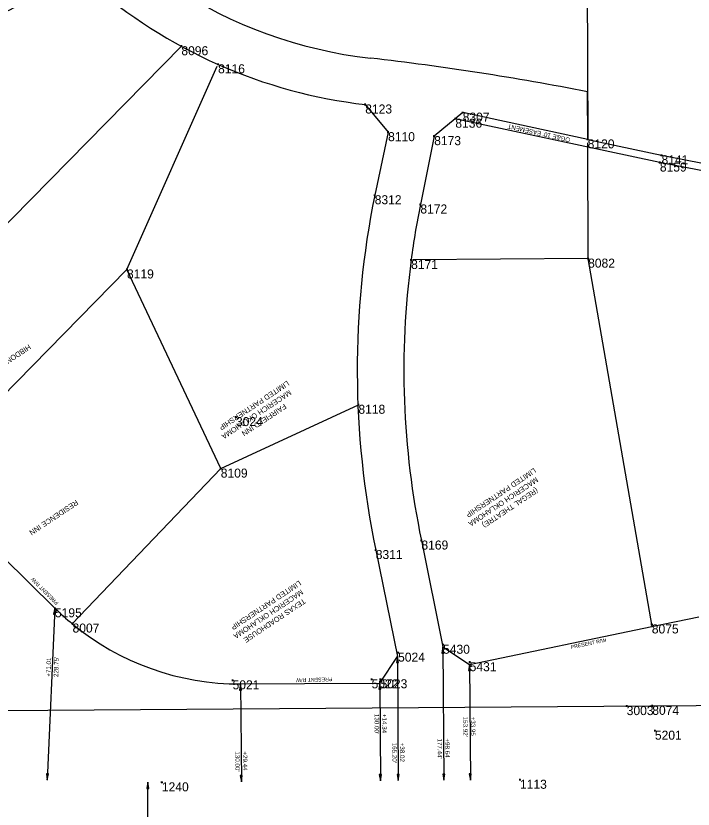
# Model space of a CAD drawing. Extents: x 2145146 to 2158053, y 137507 to 150829.
# Drawn here: x 2151434 to 2152334, y 142870 to 143925 of the extents above; entities that cross this region are included whole.
import ezdxf

# ---------------------------------------------------------------- set-up
doc = ezdxf.new("R2010")
doc.units = 0
for name, color, linetype in [('ALIGN_Cogo Points', 7, 'Continuous'), ('ALIGN_ROW Dimension', 7, 'Continuous'), ('ALIGN_ROW Line', 7, 'Continuous'), ('ALIGN_ROW Text', 7, 'Continuous'), ('PLSS_Easement', 7, 'Continuous'), ('PLSS_Property Line', 7, 'Continuous'), ('PLSS_Section Line', 7, 'Continuous'), ('PLSS_Text', 7, 'Continuous'), ('PLSS_Text_TURNED OFF', 7, 'Continuous')]:
    doc.layers.add(name, color=color, linetype=linetype)

# ---------------------------------------------------------------- blocks, each defined once
blk = doc.blocks.new('Arrowhd')
at = {"layer": 'PLSS_Property Line'}
blk.add_lwpolyline([(0.125, -0.021), (0.125, 0.021), (0, 0)], close=True, dxfattribs=at)

msp = doc.modelspace()

# ---------------------------------------------------------------- linework, layer by layer
at = {"layer": 'ALIGN_Cogo Points'}
for points in [[(2151653.6, 143884.4), (2151653.6, 143885.6), (2151653.6, 143884.4), (2151652.4, 143884.4), (2151653.6, 143884.4), (2151653.6, 143883.2), (2151653.6, 143884.4), (2151654.8, 143884.4)], [(2151702.4, 143860.4), (2151702.4, 143861.6), (2151702.4, 143860.4), (2151701.2, 143860.4), (2151702.4, 143860.4), (2151702.4, 143859.2), (2151702.4, 143860.4), (2151703.6, 143860.4)], [(2151898.1, 143806.9), (2151898.1, 143808.1), (2151898.1, 143806.9), (2151896.9, 143806.9), (2151898.1, 143806.9), (2151898.1, 143805.7), (2151898.1, 143806.9), (2151899.3, 143806.9)], [(2152027.7, 143796.1), (2152027.7, 143797.3), (2152027.7, 143796.1), (2152026.5, 143796.1), (2152027.7, 143796.1), (2152027.7, 143794.9), (2152027.7, 143796.1), (2152028.9, 143796.1)], [(2152017.9, 143788), (2152017.9, 143789.2), (2152017.9, 143788), (2152016.7, 143788), (2152017.9, 143788), (2152017.9, 143786.8), (2152017.9, 143788), (2152019.1, 143788)], [(2151928.5, 143770.1), (2151928.5, 143771.3), (2151928.5, 143770.1), (2151927.3, 143770.1), (2151928.5, 143770.1), (2151928.5, 143768.9), (2151928.5, 143770.1), (2151929.7, 143770.1)], [(2151989.8, 143764.8), (2151989.8, 143766), (2151989.8, 143764.8), (2151988.6, 143764.8), (2151989.8, 143764.8), (2151989.8, 143763.6), (2151989.8, 143764.8), (2151991, 143764.8)], [(2152193.9, 143760.5), (2152193.9, 143761.7), (2152193.9, 143760.5), (2152192.7, 143760.5), (2152193.9, 143760.5), (2152193.9, 143759.3), (2152193.9, 143760.5), (2152195.1, 143760.5)], [(2152292.1, 143739.4), (2152292.1, 143740.6), (2152292.1, 143739.4), (2152290.9, 143739.4), (2152292.1, 143739.4), (2152292.1, 143738.2), (2152292.1, 143739.4), (2152293.3, 143739.4)], [(2152289.9, 143729.7), (2152289.9, 143730.9), (2152289.9, 143729.7), (2152288.7, 143729.7), (2152289.9, 143729.7), (2152289.9, 143728.5), (2152289.9, 143729.7), (2152291.1, 143729.7)], [(2151910.7, 143686.2), (2151910.7, 143687.4), (2151910.7, 143686.2), (2151909.5, 143686.2), (2151910.7, 143686.2), (2151910.7, 143685), (2151910.7, 143686.2), (2151911.9, 143686.2)], [(2151971.4, 143673.9), (2151971.4, 143675.1), (2151971.4, 143673.9), (2151970.2, 143673.9), (2151971.4, 143673.9), (2151971.4, 143672.7), (2151971.4, 143673.9), (2151972.6, 143673.9)], [(2151959.1, 143600.1), (2151959.1, 143601.3), (2151959.1, 143600.1), (2151957.9, 143600.1), (2151959.1, 143600.1), (2151959.1, 143598.9), (2151959.1, 143600.1), (2151960.3, 143600.1)], [(2152194.5, 143601.9), (2152194.5, 143603.1), (2152194.5, 143601.9), (2152193.3, 143601.9), (2152194.5, 143601.9), (2152194.5, 143600.7), (2152194.5, 143601.9), (2152195.7, 143601.9)], [(2151581.3, 143587.5), (2151581.3, 143588.7), (2151581.3, 143587.5), (2151580.1, 143587.5), (2151581.3, 143587.5), (2151581.3, 143586.3), (2151581.3, 143587.5), (2151582.5, 143587.5)], [(2151889, 143407.5), (2151889, 143408.7), (2151889, 143407.5), (2151887.8, 143407.5), (2151889, 143407.5), (2151889, 143406.3), (2151889, 143407.5), (2151890.2, 143407.5)], [(2151726.2, 143391.1), (2151726.2, 143392.3), (2151726.2, 143391.1), (2151725, 143391.1), (2151726.2, 143391.1), (2151726.2, 143389.9), (2151726.2, 143391.1), (2151727.4, 143391.1)], [(2151706, 143322.6), (2151706, 143323.8), (2151706, 143322.6), (2151704.8, 143322.6), (2151706, 143322.6), (2151706, 143321.4), (2151706, 143322.6), (2151707.2, 143322.6)], [(2151972.8, 143226.9), (2151972.8, 143228.1), (2151972.8, 143226.9), (2151971.6, 143226.9), (2151972.8, 143226.9), (2151972.8, 143225.7), (2151972.8, 143226.9), (2151974, 143226.9)], [(2151912.1, 143214.3), (2151912.1, 143215.5), (2151912.1, 143214.3), (2151910.9, 143214.3), (2151912.1, 143214.3), (2151912.1, 143213.1), (2151912.1, 143214.3), (2151913.3, 143214.3)], [(2151485.5, 143136.8), (2151485.5, 143138), (2151485.5, 143136.8), (2151484.3, 143136.8), (2151485.5, 143136.8), (2151485.5, 143135.6), (2151485.5, 143136.8), (2151486.7, 143136.8)], [(2151508.9, 143116.5), (2151508.9, 143117.7), (2151508.9, 143116.5), (2151507.7, 143116.5), (2151508.9, 143116.5), (2151508.9, 143115.3), (2151508.9, 143116.5), (2151510.1, 143116.5)], [(2152279.2, 143115.3), (2152279.2, 143116.5), (2152279.2, 143115.3), (2152278, 143115.3), (2152279.2, 143115.3), (2152279.2, 143114.1), (2152279.2, 143115.3), (2152280.4, 143115.3)], [(2152001.6, 143088.3), (2152001.6, 143089.5), (2152001.6, 143088.3), (2152000.4, 143088.3), (2152001.6, 143088.3), (2152001.6, 143087.1), (2152001.6, 143088.3), (2152002.8, 143088.3)], [(2151941.8, 143077.8), (2151941.8, 143079), (2151941.8, 143077.8), (2151940.6, 143077.8), (2151941.8, 143077.8), (2151941.8, 143076.6), (2151941.8, 143077.8), (2151943, 143077.8)], [(2152037, 143065.1), (2152037, 143066.3), (2152037, 143065.1), (2152035.8, 143065.1), (2152037, 143065.1), (2152037, 143063.9), (2152037, 143065.1), (2152038.2, 143065.1)], [(2151721.7, 143041), (2151721.7, 143042.2), (2151721.7, 143041), (2151720.5, 143041), (2151721.7, 143041), (2151721.7, 143039.8), (2151721.7, 143041), (2151722.9, 143041)], [(2151906.6, 143042.3), (2151906.6, 143043.5), (2151906.6, 143042.3), (2151905.4, 143042.3), (2151906.6, 143042.3), (2151906.6, 143041.1), (2151906.6, 143042.3), (2151907.8, 143042.3)], [(2151918.4, 143042.4), (2151918.4, 143043.6), (2151918.4, 143042.4), (2151917.2, 143042.4), (2151918.4, 143042.4), (2151918.4, 143041.2), (2151918.4, 143042.4), (2151919.6, 143042.4)], [(2152245.8, 143006.7), (2152245.8, 143007.9), (2152245.8, 143006.7), (2152244.6, 143006.7), (2152245.8, 143006.7), (2152245.8, 143005.5), (2152245.8, 143006.7), (2152247, 143006.7)], [(2152279.8, 143007), (2152279.8, 143008.2), (2152279.8, 143007), (2152278.6, 143007), (2152279.8, 143007), (2152279.8, 143005.8), (2152279.8, 143007), (2152281, 143007)], [(2152283.3, 142974), (2152283.3, 142975.2), (2152283.3, 142974), (2152282.1, 142974), (2152283.3, 142974), (2152283.3, 142972.8), (2152283.3, 142974), (2152284.5, 142974)], [(2151627.7, 142905.3), (2151627.7, 142906.5), (2151627.7, 142905.3), (2151626.5, 142905.3), (2151627.7, 142905.3), (2151627.7, 142904.1), (2151627.7, 142905.3), (2151628.9, 142905.3)], [(2152103.9, 142908.7), (2152103.9, 142909.9), (2152103.9, 142908.7), (2152102.7, 142908.7), (2152103.9, 142908.7), (2152103.9, 142907.5), (2152103.9, 142908.7), (2152105.1, 142908.7)]]:
    msp.add_lwpolyline(points, dxfattribs=at)
at = {"layer": 'ALIGN_ROW Dimension'}
for p, q in [((2152001.3, 143085.4), (2152002.6, 142908)), ((2152036.8, 143062.2), (2152037.9, 142908.3))]:
    msp.add_line(p, q, dxfattribs=at)
for points in [[(2151485.5, 143136.8), (2151475, 142908.3)], [(2151940.8, 143072.8), (2151941.9, 142907.6)], [(2151917.3, 143037.3), (2151918.3, 142907.4)], [(2151732.4, 143036.1), (2151733.4, 142906.1)], [(2151609, 142725.2), (2151608.9, 142905.3)]]:
    msp.add_lwpolyline(points, dxfattribs=at)
at = {"layer": 'ALIGN_ROW Line'}
for p, q in [((2152279, 143112.4), (2152341.7, 143125.4)), ((2152036.8, 143062.2), (2152279, 143112.4)), ((2151817.3, 143036.7), (2151917.3, 143037.4)), ((2151732.4, 143036.1), (2151817.3, 143036.7))]:
    msp.add_line(p, q, dxfattribs=at)
msp.add_lwpolyline([(2151084.2, 143546.4), (2151084.2, 143546.4), (2151214.6, 143417.9), (2151243.2, 143375.6), (2151485.5, 143136.8)], dxfattribs=at)
for start, end in [(225.4187, 230.4847), (230.4847, 270.1873)]:
    msp.add_arc((2151731.3, 143386.2), 350.1, start, end, dxfattribs=at)
at = {"layer": 'PLSS_Easement'}
msp.add_lwpolyline([(2152358.2, 143716.3), (2152289.9, 143729.7), (2152017.9, 143788)], dxfattribs=at)
at = {"layer": 'PLSS_Property Line'}
for p, q in [((2152193.9, 143760.5), (2152193.6, 143823.8)), ((2151972.8, 143226.9), (2152001.3, 143085.4)), ((2151912.1, 143214.3), (2151940.8, 143072.8)), ((2152001.3, 143085.4), (2152036.8, 143062.2)), ((2151917.3, 143037.4), (2151940.8, 143072.8))]:
    msp.add_line(p, q, dxfattribs=at)
for points in [[(2152870.9, 145699), (2152870.9, 145699), (2152531.6, 145796.4), (2152448.8, 145508), (2152450.5, 145181.5), (2152296.2, 145180.7), (2152297.7, 144904.8), (2152369, 144834.2), (2152763.9, 144836.2), (2152765.8, 144468.4), (2152790.9, 144443.5), (2152791.4, 144359.7), (2152585.3, 144358.6), (2152560.2, 144383.4), (2152560, 144413.4), (2152243.4, 144411.8), (2152211, 144379), (2152211.5, 144277.6), (2152191.7, 144277.5), (2152193.9, 143760.5), (2152292.1, 143739.4), (2152358.2, 143726.6)], [(2151193.6, 143438.6), (2151342.3, 143589.7), (2151353.4, 143578.8), (2151653.6, 143884.4)], [(2151309.3, 143310.5), (2151581.3, 143587.5), (2151701.2, 143857.7)], [(2151898.1, 143806.9), (2151928.5, 143770.1), (2151910.7, 143686.2)], [(2152193.9, 143760.5), (2152027.7, 143796.1), (2151989.8, 143764.8), (2151971.4, 143673.9)], [(2152194.5, 143601.9), (2152193.9, 143756)], [(2152279.7, 143112.6), (2152194.5, 143601.9), (2151961.5, 143600.1)], [(2151706, 143322.6), (2151581.3, 143587.5)], [(2151508.5, 143116.1), (2151706, 143322.6), (2151889, 143407.5)]]:
    msp.add_lwpolyline(points, dxfattribs=at)
for centre, radius, start, end in [((2151975.9, 144476.6), 612.3, 210.5623, 263.3737), ((2151975.9, 144476.6), 674.3, 228.7686, 246.0665), ((2151281.7, 144214.2), 315.9, 274.098, 307.806), ((2151975.9, 144476.6), 674.3, 246.0665, 263.3737), ((2151496.3, 140278.5), 3613.2, 78.8734, 83.5018), ((2153064.5, 143453.7), 1177, 168.6079, 191.7369), ((2153064.5, 143453.7), 1115, 168.6079, 172.4527), ((2153064.5, 143453.7), 1115, 172.4527, 191.7369)]:
    msp.add_arc(centre, radius, start, end, dxfattribs=at)
at = {"layer": 'PLSS_Section Line'}
msp.add_lwpolyline([(2150921.7, 142997.3), (2153570, 143016.2)], dxfattribs=at)

# ---------------------------------------------------------------- block references
at = {"layer": 'ALIGN_ROW Dimension', "yscale": 65}
for p, xscale, rotation in [((2151485.5, 143136.8), 65, -93.1211016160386), ((2152001.3, 143085.4), 64.99999999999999, -89.59270350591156), ((2151940.8, 143072.8), 64.99999999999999, -89.59270350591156), ((2152036.8, 143062.2), 64.99999999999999, -89.59270350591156), ((2151917.3, 143037.4), 64.99999999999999, -89.59270350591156), ((2151732.4, 143036.1), 65, -90.00000000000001), ((2151475, 142908.4), 64.99999999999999, 86.98495102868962), ((2151733.4, 142906.1), 64.99999999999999, 90.89458591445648), ((2151918.3, 142907.4), 64.99999999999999, 90.89458591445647), ((2151941.9, 142907.6), 64.99999999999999, 90.89458591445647), ((2152002.6, 142908), 64.99999999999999, 90.89458591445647), ((2152037.9, 142908.3), 64.99999999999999, 90.89458591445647), ((2151608.9, 142905.3), 65, -89.96586345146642)]:
    msp.add_blockref('Arrowhd', p, dxfattribs=dict(at, xscale=xscale, rotation=rotation))

# ---------------------------------------------------------------- texts
at = {"layer": 'ALIGN_Cogo Points'}
for s, p in [('8096', (2151653.6, 143872.4)), ('8116', (2151702.4, 143848.4)), ('8123', (2151898.1, 143794.9)), ('8136', (2152017.9, 143776)), ('8307', (2152027.7, 143784.1)), ('8110', (2151928.5, 143758.1)), ('8173', (2151989.8, 143752.8)), ('8120', (2152193.9, 143748.5)), ('8141', (2152292.1, 143727.4)), ('8159', (2152289.9, 143717.7)), ('8312', (2151910.7, 143674.2)), ('8172', (2151971.4, 143661.9)), ('8171', (2151959.1, 143588.1)), ('8082', (2152194.5, 143589.9)), ('8119', (2151581.3, 143575.5)), ('8118', (2151889, 143395.5)), ('3024', (2151726.2, 143379.1)), ('8109', (2151706, 143310.6)), ('8169', (2151972.8, 143214.9)), ('8311', (2151912.1, 143202.3)), ('5195', (2151485.5, 143124.8)), ('8007', (2151508.9, 143104.5)), ('8075', (2152279.2, 143103.3)), ('5430', (2152001.6, 143076.3)), ('5024', (2151941.8, 143065.8)), ('5431', (2152037, 143053.1)), ('5021', (2151721.7, 143029)), ('5022', (2151906.6, 143030.3)), ('5023', (2151918.4, 143030.4)), ('3003', (2152245.8, 142994.7)), ('8074', (2152279.8, 142995)), ('5201', (2152283.3, 142962)), ('1240', (2151627.7, 142893.3)), ('1113', (2152103.9, 142896.7))]:
    msp.add_text(s, height=12, dxfattribs=at).set_placement(p)
at = {"layer": 'ALIGN_ROW Dimension'}
for s, rotation, p in [('+71.01', 88.19, (2151479.7, 143045.6)), ("228.75'", 88.19, (2151489.8, 143045.3)), ("130.00'", 270, (2151910.6, 142996.3)), ('+14.34', 270, (2151920.8, 142996.3)), ("153.92'", 270, (2152028.4, 142992.7)), ('+33.95', 270, (2152038.6, 142992.7)), ('+98.64', 270, (2152004.5, 142963.7)), ("165.20'", 270, (2151934.1, 142958)), ('+38.02', 270, (2151944.3, 142958)), ("177.44'", 270, (2151994.3, 142963.7)), ("130.00'", 270, (2151725.3, 142946.5)), ('+29.44', 270, (2151735.4, 142946.5))]:
    msp.add_text(s, height=6, rotation=rotation, dxfattribs=at).set_placement(p)
at = {"layer": 'ALIGN_ROW Text'}
for rotation, p in [(135.018, (2151490.7, 143144.3)), (11.4188, (2152171.9, 143082.7)), (181.6818, (2151854.2, 143044.9))]:
    msp.add_text('PRESENT R/W', height=5, rotation=rotation, dxfattribs=at).set_placement(p)
at = {"layer": 'PLSS_Text'}
msp.add_text("OG&E 10' EASEMENT", height=6, rotation=167.3071, dxfattribs=at).set_placement((2152171.1, 143762.3))
at = {"layer": 'PLSS_Text_TURNED OFF'}
for s, p in [('HIBDON TIRES PLUS', (2151450.5, 143488.3)), ('LIMITED PARTNERSHIP', (2151794.1, 143439.9)), ('MACERICH OKLAHOMA', (2151796.9, 143427.7)), ('FAIRFIELD INN', (2151790.3, 143409.3)), ('LIMITED PARTNERSHIP', (2152122.3, 143323.8)), ('MACERICH OKLAHOMA', (2152125.1, 143311.6)), ('(REGAL THEATRE)', (2152125, 143297.5)), ('RESIDENCE INN', (2151513.5, 143281.4)), ('LIMITED PARTNERSHIP', (2151809.9, 143174.2)), ('MACERICH OKLAHOMA', (2151812.7, 143162.1)), ('TEXAS ROADHOUSE', (2151815.9, 143150.1))]:
    msp.add_text(s, height=7, rotation=213.7516, dxfattribs=at).set_placement(p)

doc.saveas('drawing.dxf')
